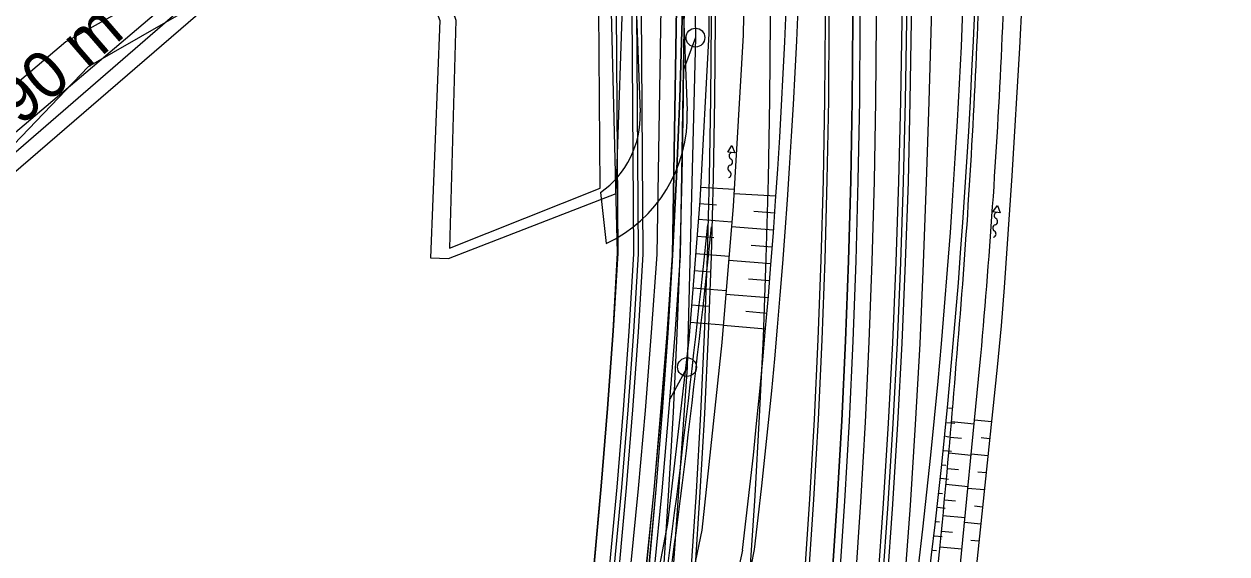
# Model space of a CAD drawing. Extents: x -439827 to -439102, y -1131353 to -1129707.
# Drawn here: x -439555.8 to -439479.1, y -1130393.9 to -1130360.1 of the extents above; entities that cross this region are included whole.
import ezdxf

# ---------------------------------------------------------------- set-up
doc = ezdxf.new("R2010")
doc.units = 0
for name, color, linetype in [('Vrstva 1', 7, 'Continuous'), ('Vrstva 11', 7, 'Continuous'), ('Vrstva 18', 7, 'Continuous'), ('Vrstva 3', 7, 'Continuous'), ('Vrstva 4', 7, 'Continuous'), ('Vrstva 5', 7, 'Continuous'), ('Vrstva 52', 7, 'Continuous'), ('Vrstva 53', 7, 'Continuous'), ('Vrstva 54', 7, 'Continuous'), ('Vrstva 8', 7, 'Continuous'), ('Vrstva 9', 7, 'Continuous')]:
    doc.layers.add(name, color=color, linetype=linetype)

msp = doc.modelspace()

# ---------------------------------------------------------------- linework, layer by layer
at = {"layer": 'Vrstva 1'}
msp.add_lwpolyline([(-439571.132, -1130382.304), (-439541.901, -1130357.085), (-439531.775, -1130353.263), (-439529.265, -1130359.915), (-439529.864, -1130375.044), (-439528.712, -1130375.089), (-439518.019, -1130370.936), (-439517.541, -1130356.511), (-439521.076, -1130347.723), (-439518.492, -1130346.684), (-439518.497, -1130338.266), (-439545.626, -1130351.066), (-439561.77, -1130361.383)], dxfattribs=at)
at = {"layer": 'Vrstva 11'}
msp.add_lwpolyline([(-439517.844, -1130344.818), (-439537.232, -1130352.412), (-439553.102, -1130361.278), (-439561.554, -1130368.442), (-439569.834, -1130377.42), (-439579.582, -1130385.476), (-439589.25, -1130390.818), (-439602.494, -1130394.582), (-439614.18, -1130396.886)], dxfattribs=at)
at = {"layer": 'Vrstva 18'}
for p, q in [((-439512.977, -1130361.005), (-439513.743, -1130363.062)), ((-439513.515, -1130381.999), (-439514.617, -1130384.044))]:
    msp.add_line(p, q, dxfattribs=at)
msp.add_lwpolyline([(-439516.306, -1130300.572), (-439516.135, -1130302.12), (-439514.522, -1130319.043), (-439513.307, -1130340.008), (-439512.977, -1130361.005), (-439513.515, -1130381.999), (-439515.113, -1130405.146), (-439521.59, -1130451.589), (-439532.085, -1130497.339)], dxfattribs=at)
for centre in [(-439512.977, -1130361.005), (-439513.515, -1130381.999)]:
    msp.add_circle(centre, 0.6, dxfattribs=at)
at = {"layer": 'Vrstva 4'}
for points in [[(-439572.44, -1130382.24), (-439542.04, -1130355.91), (-439531.241, -1130351.299), (-439529.58, -1130350.59), (-439527.74, -1130349.8), (-439522.37, -1130347.51), (-439519.25, -1130346.18), (-439519.3, -1130340.15), (-439519.35, -1130339.39), (-439529.72, -1130344.26), (-439531.53, -1130345.11), (-439544.24, -1130351.07), (-439561.14, -1130361.82)], [(-439531.241, -1130351.299), (-439528.25, -1130359.898), (-439528.649, -1130374.425), (-439519.04, -1130370.59), (-439519.16, -1130356.35), (-439522.37, -1130347.51), (-439527.74, -1130349.8), (-439529.58, -1130350.59), (-439531.241, -1130351.299)]]:
    msp.add_lwpolyline(points, dxfattribs=at)
at = {"layer": 'Vrstva 5'}
for points in [[(-439500.807, -1130287.702), (-439499.35, -1130297.934), (-439499.339, -1130298.122), (-439499.269, -1130304.303), (-439499.386, -1130308.339), (-439499.918, -1130318.741), (-439500.398, -1130329.088), (-439500.014, -1130339.36), (-439499.825, -1130349.636), (-439499.83, -1130359.912), (-439499.906, -1130365.048), (-439500.03, -1130370.184), (-439500.203, -1130375.317), (-439500.424, -1130380.449), (-439500.695, -1130385.578), (-439501.013, -1130390.703), (-439501.381, -1130395.826)], [(-439500.51, -1130287.662), (-439499.052, -1130297.9), (-439499.041, -1130298.087), (-439498.971, -1130304.272), (-439499.087, -1130308.311), (-439499.619, -1130318.718), (-439500.099, -1130329.071), (-439499.714, -1130339.349), (-439499.525, -1130349.631), (-439499.53, -1130359.912), (-439499.606, -1130365.052), (-439499.73, -1130370.19), (-439499.903, -1130375.327), (-439500.125, -1130380.462), (-439500.395, -1130385.593), (-439500.714, -1130390.722), (-439501.081, -1130395.847)], [(-439500.213, -1130287.622), (-439498.754, -1130297.865), (-439498.743, -1130298.052), (-439498.673, -1130304.24), (-439498.789, -1130308.282), (-439499.32, -1130318.695), (-439499.799, -1130329.054), (-439499.414, -1130339.338), (-439499.225, -1130349.625), (-439499.23, -1130359.913), (-439499.306, -1130365.056), (-439499.43, -1130370.197), (-439499.603, -1130375.337), (-439499.825, -1130380.474), (-439500.095, -1130385.609), (-439500.414, -1130390.741), (-439500.782, -1130395.869)], [(-439509.459, -1130288.877), (-439508.184, -1130298.965), (-439508.163, -1130299.148), (-439507.499, -1130305.162), (-439507.105, -1130309.086), (-439506.226, -1130319.226), (-439505.547, -1130329.381), (-439505.07, -1130339.547), (-439504.794, -1130349.722), (-439504.719, -1130359.899), (-439504.757, -1130364.988), (-439504.845, -1130370.076), (-439504.984, -1130375.163), (-439505.173, -1130380.249), (-439505.413, -1130385.332), (-439505.702, -1130390.413), (-439506.042, -1130395.491)], [(-439509.212, -1130288.843), (-439507.936, -1130298.936), (-439507.915, -1130299.119), (-439507.251, -1130305.136), (-439506.856, -1130309.062), (-439505.977, -1130319.206), (-439505.298, -1130329.367), (-439504.82, -1130339.538), (-439504.544, -1130349.717), (-439504.469, -1130359.9), (-439504.507, -1130364.991), (-439504.596, -1130370.082), (-439504.734, -1130375.171), (-439504.923, -1130380.259), (-439505.163, -1130385.345), (-439505.453, -1130390.428), (-439505.793, -1130395.509)], [(-439507.725, -1130288.641), (-439506.446, -1130298.762), (-439506.425, -1130298.946), (-439505.759, -1130304.98), (-439505.363, -1130308.917), (-439504.481, -1130319.092), (-439503.8, -1130329.281), (-439503.321, -1130339.483), (-439503.044, -1130349.691), (-439502.969, -1130359.904), (-439503.007, -1130365.01), (-439503.096, -1130370.115), (-439503.235, -1130375.22), (-439503.425, -1130380.322), (-439503.665, -1130385.423), (-439503.956, -1130390.521), (-439504.297, -1130395.616)], [(-439507.71, -1130288.639), (-439506.431, -1130298.761), (-439506.41, -1130298.944), (-439505.744, -1130304.979), (-439505.348, -1130308.916), (-439504.466, -1130319.09), (-439503.785, -1130329.281), (-439503.306, -1130339.482), (-439503.029, -1130349.691), (-439502.954, -1130359.904), (-439502.992, -1130365.01), (-439503.081, -1130370.116), (-439503.22, -1130375.22), (-439503.41, -1130380.323), (-439503.65, -1130385.424), (-439503.941, -1130390.522), (-439504.282, -1130395.617)], [(-439503.798, -1130395.652), (-439503.456, -1130390.552), (-439503.166, -1130385.449), (-439502.925, -1130380.344), (-439502.735, -1130375.236), (-439502.596, -1130370.126), (-439502.507, -1130365.016), (-439502.469, -1130359.904), (-439502.544, -1130349.683), (-439502.822, -1130339.464), (-439503.301, -1130329.253), (-439503.982, -1130319.053), (-439504.865, -1130308.871), (-439505.262, -1130304.928), (-439505.928, -1130298.89), (-439505.95, -1130298.702), (-439507.23, -1130288.574)], [(-439506.239, -1130288.44), (-439504.956, -1130298.589), (-439504.935, -1130298.773), (-439504.267, -1130304.825), (-439503.87, -1130308.773), (-439502.985, -1130318.977), (-439502.303, -1130329.196), (-439501.822, -1130339.427), (-439501.544, -1130349.666), (-439501.469, -1130359.907), (-439501.507, -1130365.028), (-439501.596, -1130370.149), (-439501.736, -1130375.268), (-439501.926, -1130380.386), (-439502.167, -1130385.501), (-439502.458, -1130390.614), (-439502.8, -1130395.724)], [(-439512.928, -1130289.348), (-439511.661, -1130299.371), (-439511.64, -1130299.553), (-439510.981, -1130305.526), (-439510.589, -1130309.422), (-439509.716, -1130319.493), (-439509.042, -1130329.579), (-439508.568, -1130339.677), (-439508.293, -1130349.782), (-439508.219, -1130359.89), (-439508.257, -1130364.945), (-439508.345, -1130369.998), (-439508.482, -1130375.051), (-439508.67, -1130380.102), (-439508.908, -1130385.15), (-439509.195, -1130390.197), (-439509.533, -1130395.24)], [(-439519.616, -1130290.255), (-439518.365, -1130300.153), (-439518.345, -1130300.332), (-439517.694, -1130306.227), (-439517.307, -1130310.072), (-439516.446, -1130320.01), (-439515.781, -1130329.963), (-439515.313, -1130339.927), (-439515.042, -1130349.898), (-439515.448, -1130374.826), (-439515.789, -1130379.802), (-439516.179, -1130384.772), (-439516.619, -1130389.737), (-439517.107, -1130394.695), (-439517.645, -1130399.647), (-439518.231, -1130404.592), (-439518.866, -1130409.529), (-439519.549, -1130414.458), (-439520.281, -1130419.379), (-439521.062, -1130424.29), (-439521.891, -1130429.192), (-439522.768, -1130434.084), (-439523.693, -1130438.966), (-439525.38, -1130448.752)], [(-439518.641, -1130290.125), (-439517.389, -1130300.036), (-439517.367, -1130300.223), (-439516.716, -1130306.125), (-439516.328, -1130309.982), (-439515.465, -1130319.937), (-439514.798, -1130329.909), (-439514.33, -1130339.893), (-439514.058, -1130349.896), (-439514.464, -1130374.872), (-439514.808, -1130379.878), (-439515.199, -1130384.859), (-439515.639, -1130389.833), (-439516.129, -1130394.801), (-439516.667, -1130399.763), (-439517.254, -1130404.718), (-439517.891, -1130409.665), (-439518.575, -1130414.604), (-439519.309, -1130419.534), (-439520.091, -1130424.455), (-439520.922, -1130429.367), (-439521.8, -1130434.269), (-439522.464, -1130437.768)], [(-439518.625, -1130290.121), (-439517.373, -1130300.033), (-439517.351, -1130300.22), (-439516.7, -1130306.122), (-439516.312, -1130309.979), (-439515.449, -1130319.933), (-439514.782, -1130329.906), (-439514.314, -1130339.89), (-439514.042, -1130349.893), (-439514.448, -1130374.869), (-439514.792, -1130379.875), (-439515.183, -1130384.855), (-439515.623, -1130389.83), (-439516.113, -1130394.798), (-439516.651, -1130399.76), (-439517.238, -1130404.714), (-439517.874, -1130409.661), (-439518.559, -1130414.6), (-439519.293, -1130419.531), (-439520.075, -1130424.452), (-439520.906, -1130429.364), (-439521.784, -1130434.266), (-439522.448, -1130437.765)], [(-439518.13, -1130290.054), (-439516.876, -1130299.972), (-439516.854, -1130300.163), (-439516.202, -1130306.069), (-439515.814, -1130309.932), (-439514.95, -1130319.895), (-439514.283, -1130329.878), (-439513.814, -1130339.871), (-439513.542, -1130349.89), (-439513.948, -1130374.89), (-439514.293, -1130379.912), (-439514.684, -1130384.897), (-439515.125, -1130389.876), (-439515.615, -1130394.849), (-439516.154, -1130399.816), (-439516.742, -1130404.776), (-439517.379, -1130409.728), (-439518.064, -1130414.671), (-439518.799, -1130419.607), (-439519.582, -1130424.533), (-439520.413, -1130429.45), (-439521.293, -1130434.356), (-439521.956, -1130437.858)], [(-439518.378, -1130290.087), (-439517.124, -1130300.008), (-439517.103, -1130300.188), (-439516.451, -1130306.097), (-439516.063, -1130309.952), (-439515.199, -1130319.914), (-439514.533, -1130329.892), (-439514.064, -1130339.881), (-439513.793, -1130349.877), (-439513.719, -1130359.876), (-439513.756, -1130364.876), (-439513.843, -1130369.875), (-439513.98, -1130374.874), (-439514.165, -1130379.87), (-439514.4, -1130384.864), (-439514.685, -1130389.856), (-439515.019, -1130394.845)], [(-439516.643, -1130289.852), (-439515.386, -1130299.805), (-439515.365, -1130299.986), (-439514.71, -1130305.915), (-439514.321, -1130309.783), (-439513.455, -1130319.78), (-439512.786, -1130329.792), (-439512.315, -1130339.816), (-439512.043, -1130349.847), (-439511.969, -1130359.881), (-439512.007, -1130364.898), (-439512.094, -1130369.914), (-439512.23, -1130374.93), (-439512.417, -1130379.944), (-439512.653, -1130384.955), (-439512.938, -1130389.965), (-439513.273, -1130394.971)], [(-439516.396, -1130289.818), (-439515.137, -1130299.776), (-439515.116, -1130299.957), (-439514.462, -1130305.889), (-439514.072, -1130309.759), (-439513.205, -1130319.761), (-439512.536, -1130329.778), (-439512.065, -1130339.807), (-439511.793, -1130349.842), (-439511.719, -1130359.881), (-439511.757, -1130364.901), (-439511.844, -1130369.92), (-439511.981, -1130374.938), (-439512.167, -1130379.954), (-439512.403, -1130384.968), (-439512.689, -1130389.98), (-439513.024, -1130394.989)], [(-439526.283, -1130291.16), (-439524.956, -1130300.922), (-439524.934, -1130301.099), (-439523.187, -1130306.8), (-439522.037, -1130310.529), (-439519.205, -1130320.222), (-439517.874, -1130330.082), (-439517.183, -1130339.996), (-439516.795, -1130349.929), (-439516.633, -1130374.788), (-439516.929, -1130379.754), (-439517.285, -1130384.714), (-439517.692, -1130389.67), (-439518.148, -1130394.62), (-439518.654, -1130399.564), (-439519.201, -1130404.503), (-439519.799, -1130409.434), (-439520.455, -1130414.357), (-439521.161, -1130419.271), (-439521.927, -1130424.176), (-439522.744, -1130429.071), (-439523.606, -1130433.957), (-439524.653, -1130438.811), (-439526.345, -1130448.576)], [(-439525.985, -1130291.12), (-439524.658, -1130300.887), (-439524.636, -1130301.064), (-439522.889, -1130306.769), (-439521.739, -1130310.5), (-439518.905, -1130320.199), (-439517.574, -1130330.065), (-439516.884, -1130339.985), (-439516.495, -1130349.923), (-439516.334, -1130374.798), (-439516.629, -1130379.766), (-439516.985, -1130384.73), (-439517.392, -1130389.689), (-439517.848, -1130394.642), (-439518.355, -1130399.589), (-439518.903, -1130404.53), (-439519.5, -1130409.464), (-439520.157, -1130414.39), (-439520.863, -1130419.308), (-439521.63, -1130424.215), (-439522.447, -1130429.113), (-439523.309, -1130434.002), (-439524.357, -1130438.859), (-439526.049, -1130448.63)], [(-439531.539, -1130291.874), (-439530.307, -1130301.547), (-439530.286, -1130301.722), (-439527.564, -1130307.257), (-439525.735, -1130310.887), (-439521.155, -1130320.371), (-439519.39, -1130330.168), (-439518.706, -1130340.053), (-439518.577, -1130349.959), (-439517.962, -1130374.745), (-439518.249, -1130379.698), (-439518.603, -1130384.646), (-439519.007, -1130389.589), (-439519.458, -1130394.526), (-439520.072, -1130399.448), (-439520.715, -1130404.364), (-439521.204, -1130409.291), (-439521.904, -1130414.195), (-439522.655, -1130419.089), (-439523.47, -1130423.973), (-439524.331, -1130428.846), (-439525.233, -1130433.71), (-439526.317, -1130438.541), (-439527.99, -1130448.276)], [(-439527.561, -1130291.334), (-439526.238, -1130301.072), (-439526.215, -1130301.248), (-439524.47, -1130306.934), (-439523.321, -1130310.653), (-439520.491, -1130320.32), (-439519.162, -1130330.155), (-439518.472, -1130340.044), (-439518.085, -1130349.951), (-439517.923, -1130374.746), (-439518.218, -1130379.699), (-439518.573, -1130384.647), (-439518.979, -1130389.59), (-439519.434, -1130394.528), (-439519.94, -1130399.459), (-439520.486, -1130404.385), (-439521.082, -1130409.303), (-439521.737, -1130414.213), (-439522.442, -1130419.115), (-439523.206, -1130424.007), (-439524.021, -1130428.89), (-439524.881, -1130433.763), (-439525.926, -1130438.604), (-439527.614, -1130448.345)], [(-439526.58, -1130291.201), (-439525.254, -1130300.957), (-439525.232, -1130301.134), (-439523.485, -1130306.831), (-439522.336, -1130310.558), (-439519.504, -1130320.245), (-439518.173, -1130330.099), (-439517.483, -1130340.007), (-439517.095, -1130349.934), (-439516.933, -1130374.778), (-439517.229, -1130379.741), (-439517.584, -1130384.699), (-439517.991, -1130389.652), (-439518.447, -1130394.599), (-439518.953, -1130399.54), (-439519.5, -1130404.475), (-439520.097, -1130409.404), (-439520.753, -1130414.323), (-439521.459, -1130419.235), (-439522.225, -1130424.137), (-439523.041, -1130429.029), (-439523.903, -1130433.912), (-439524.949, -1130438.762), (-439526.64, -1130448.522)], [(-439497.706, -1130297.932), (-439497.484, -1130304.116), (-439497.558, -1130308.163), (-439498.078, -1130318.6), (-439498.345, -1130328.971), (-439497.993, -1130339.285), (-439498.048, -1130349.605), (-439497.962, -1130359.916), (-439498.093, -1130365.071), (-439498.274, -1130370.223), (-439498.454, -1130375.374), (-439498.684, -1130380.522), (-439498.964, -1130385.668), (-439499.293, -1130390.81), (-439499.672, -1130395.949)], [(-439514.043, -1130349.881), (-439513.834, -1130359.876), (-439513.99, -1130364.873), (-439514.196, -1130369.868), (-439514.451, -1130374.858), (-439514.755, -1130379.845), (-439515.108, -1130384.828), (-439515.511, -1130389.805), (-439515.963, -1130394.777), (-439516.464, -1130399.744), (-439517.013, -1130404.703), (-439517.612, -1130409.657), (-439518.26, -1130414.602), (-439518.956, -1130419.54), (-439519.701, -1130424.47), (-439520.495, -1130429.391), (-439521.337, -1130434.302), (-439521.987, -1130437.883)], [(-439514.043, -1130349.881), (-439513.819, -1130359.876), (-439513.975, -1130364.873), (-439514.181, -1130369.868), (-439514.436, -1130374.859), (-439514.74, -1130379.846), (-439515.093, -1130384.828), (-439515.496, -1130389.806), (-439515.948, -1130394.778), (-439516.449, -1130399.745), (-439516.998, -1130404.705), (-439517.597, -1130409.658), (-439518.245, -1130414.604), (-439518.941, -1130419.542), (-439519.686, -1130424.472), (-439520.48, -1130429.393), (-439521.322, -1130434.304), (-439521.973, -1130437.888)]]:
    msp.add_lwpolyline(points, dxfattribs=at)
at = {"layer": 'Vrstva 52'}
for p, q in [((-439512.138, -1130341.236), (-439512.128, -1130360.752)), ((-439509.478, -1130341.242), (-439509.942, -1130360.852)), ((-439513.49, -1130365.664), (-439514.336, -1130342.858)), ((-439516.488, -1130365.774), (-439516.958, -1130353.074)), ((-439519.02, -1130370.876), (-439518.67, -1130374.131)), ((-439496.838, -1130402.16), (-439494.842, -1130381.908)), ((-439493.756, -1130382.006), (-439495.866, -1130402.29)), ((-439509.972, -1130393.674), (-439521.244, -1130443.404))]:
    msp.add_line(p, q, dxfattribs=at)
for points in [[(-439714.406, -1130412.208), (-439698.562, -1130412.132), (-439686.994, -1130411.394), (-439659.688, -1130406.848), (-439631.008, -1130400.752), (-439604.978, -1130396.618), (-439592.268, -1130393.564), (-439572.812, -1130381.312), (-439556.454, -1130367.154), (-439543.11, -1130355.814), (-439532.998, -1130352.028), (-439506.332, -1130342.096), (-439504.524, -1130343.242), (-439465.198, -1130328.028)], [(-439491.888, -1130341.28), (-439491.988, -1130351.896), (-439492.022, -1130355.78), (-439492.32, -1130361.666)], [(-439512.128, -1130360.752), (-439512.694, -1130371.4), (-439513.406, -1130380.232)], [(-439509.942, -1130360.852), (-439510.574, -1130371.752), (-439511.286, -1130380.424)], [(-439492.32, -1130361.666), (-439492.82, -1130369.814), (-439493.3, -1130376.93), (-439493.482, -1130379.381), (-439493.756, -1130382.006)], [(-439513.406, -1130380.232), (-439514.748, -1130391.96), (-439516.212, -1130399.548)], [(-439511.286, -1130380.424), (-439512.56, -1130392.384), (-439514.122, -1130399.83)]]:
    msp.add_lwpolyline(points, dxfattribs=at)
for centre, radius, start, end in [((-439956.286, -1130340.256), 460.75, 350.84867, 9.74494), ((-439956.286, -1130340.256), 449.5, 353.17483, 9.74494), ((-439956.286, -1130340.256), 450.25, 353.19326, 9.74494), ((-439956.286, -1130340.256), 461.5, 353.07589, 8.43792), ((-439956.299, -1130340.932), 461.722, 357.4418, 359.95753), ((-439956.27, -1130340.037), 463.324, 357.33079, 359.84653), ((-439956.383, -1130341.613), 461.776, 355.011, 357.52671), ((-439956.26, -1130340.026), 463.314, 354.81363, 357.32934), ((-439522.491, -1130365.981), 6, 305.32942, 1.97347), ((-439522.491, -1130365.981), 9, 295.1138, 1.97347), ((-439956.994, -1130346.588), 461.98, 353.11656, 355.63229), ((-439689.719, -1130355.454), 184.5, 347.22878, 348.06158)]:
    msp.add_arc(centre, radius, start, end, dxfattribs=at)
at = {"layer": 'Vrstva 53'}
for p, q in [((-439512.65, -1130370.544), (-439510.51, -1130370.658)), ((-439512.708, -1130371.574), (-439511.642, -1130371.66)), ((-439507.85, -1130371.116), (-439510.528, -1130370.96)), ((-439507.926, -1130372.2), (-439509.26, -1130372.09)), ((-439512.788, -1130372.568), (-439510.656, -1130372.744)), ((-439508.008, -1130373.27), (-439510.682, -1130373.066)), ((-439512.876, -1130373.664), (-439511.812, -1130373.75)), ((-439512.964, -1130374.756), (-439510.836, -1130374.93)), ((-439508.092, -1130374.354), (-439509.43, -1130374.246)), ((-439508.174, -1130375.426), (-439510.858, -1130375.218)), ((-439513.054, -1130375.85), (-439511.988, -1130375.936)), ((-439513.142, -1130376.942), (-439511.014, -1130377.116)), ((-439508.258, -1130376.51), (-439509.602, -1130376.4)), ((-439508.34, -1130377.58), (-439511.036, -1130377.372)), ((-439513.23, -1130378.036), (-439512.166, -1130378.122)), ((-439508.428, -1130378.578), (-439509.772, -1130378.466)), ((-439513.318, -1130379.128), (-439511.194, -1130379.302)), ((-439508.518, -1130379.574), (-439511.198, -1130379.354)), ((-439496.848, -1130384.598), (-439496.628, -1130384.622)), ((-439496.664, -1130385.472), (-439495.208, -1130385.614)), ((-439494.118, -1130385.484), (-439495.184, -1130385.38)), ((-439496.95, -1130385.528), (-439496.454, -1130385.584)), ((-439497.048, -1130386.41), (-439496.826, -1130386.434)), ((-439496.746, -1130386.468), (-439496.026, -1130386.54)), ((-439494.232, -1130386.574), (-439494.762, -1130386.518)), ((-439497.146, -1130387.308), (-439496.65, -1130387.364)), ((-439496.828, -1130387.466), (-439495.404, -1130387.606)), ((-439494.344, -1130387.658), (-439495.398, -1130387.554)), ((-439497.246, -1130388.222), (-439497.024, -1130388.246)), ((-439496.92, -1130388.464), (-439496.212, -1130388.534)), ((-439497.342, -1130389.088), (-439496.846, -1130389.142)), ((-439494.458, -1130388.748), (-439494.982, -1130388.692)), ((-439497.444, -1130390.034), (-439497.224, -1130390.058)), ((-439497.016, -1130389.46), (-439495.6, -1130389.6)), ((-439494.57, -1130389.832), (-439495.614, -1130389.728)), ((-439497.112, -1130390.456), (-439496.406, -1130390.526)), ((-439497.544, -1130390.932), (-439497.058, -1130390.986)), ((-439497.208, -1130391.452), (-439495.796, -1130391.592)), ((-439494.684, -1130390.92), (-439495.202, -1130390.866)), ((-439497.644, -1130391.846), (-439497.422, -1130391.87)), ((-439494.796, -1130392.004), (-439495.828, -1130391.904)), ((-439497.742, -1130392.744), (-439497.252, -1130392.798)), ((-439497.304, -1130392.448), (-439496.6, -1130392.518)), ((-439494.91, -1130393.094), (-439495.422, -1130393.04)), ((-439497.842, -1130393.658), (-439497.622, -1130393.682)), ((-439497.4, -1130393.446), (-439495.994, -1130393.584))]:
    msp.add_line(p, q, dxfattribs=at)
at = {"layer": 'Vrstva 54'}
for points in [[(-439510.47, -1130368.356), (-439510.92, -1130368.314), (-439510.65, -1130367.886)], [(-439493.566, -1130372.166), (-439494.014, -1130372.114), (-439493.734, -1130371.694)]]:
    msp.add_lwpolyline(points, close=True, dxfattribs=at)
for centre, radius, start, end in [((-439510.618, -1130368.541), 0.219, 108.95119, 239.79586), ((-439510.7, -1130369.335), 0.216, 108.68561, 240.57213), ((-439510.822, -1130368.923), 0.214, 284.56238, 64.02729), ((-439510.916, -1130369.713), 0.22, 289.26644, 59.91361), ((-439493.717, -1130372.349), 0.219, 107.71854, 238.56321), ((-439493.815, -1130373.141), 0.216, 107.45296, 239.33948), ((-439493.929, -1130372.727), 0.214, 283.32973, 62.79464), ((-439494.04, -1130373.515), 0.22, 288.03379, 58.68096)]:
    msp.add_arc(centre, radius, start, end, dxfattribs=at)
at = {"layer": 'Vrstva 8'}
for radius, end in [(754.238, 354.151509), (754.488, 354.143651)]:
    msp.add_arc((-440262.504, -1130296.072), radius, 349.157783, end, dxfattribs=at)
at = {"layer": 'Vrstva 9'}
msp.add_lwpolyline([(-439517.528, -1130346.522), (-439536.884, -1130354.376), (-439551.674, -1130362.86), (-439567.784, -1130379.662), (-439588.862, -1130392.166), (-439602.298, -1130395.778), (-439614.18, -1130396.886)], dxfattribs=at)

# ---------------------------------------------------------------- texts
at = {"layer": 'Vrstva 3'}
msp.add_text('- 90 m', height=3, rotation=40.8752, dxfattribs=at).set_placement((-439557.843, -1130368.298))

doc.saveas('drawing.dxf')
